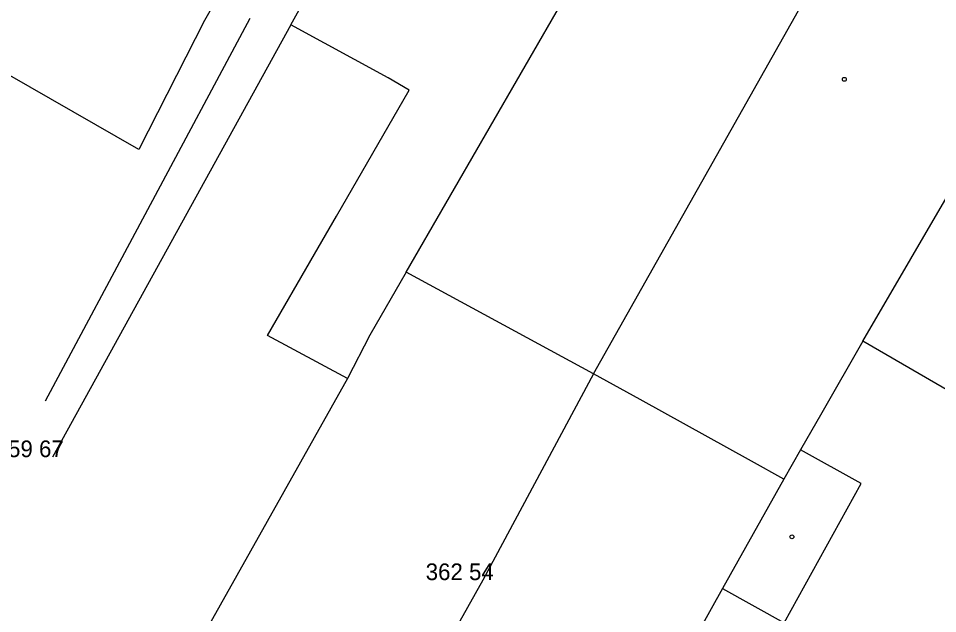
# Model space of a CAD drawing. Extents: x -688316 to -688024, y -973785 to -973591.
# Drawn here: x -688191.59 to -688150.19, y -973719.16 to -973692.34 of the extents above; entities that cross this region are included whole.
import ezdxf

# ---------------------------------------------------------------- set-up
doc = ezdxf.new("R2010")
doc.units = 0
for name, color, linetype in [('Vrstva 12_kanalizace SCVAK', 7, 'Continuous'), ('Vrstva 3', 7, 'Continuous'), ('Vrstva 5', 7, 'Continuous'), ('Vrstva 58', 7, 'Continuous'), ('Vrstva 7', 7, 'Continuous')]:
    doc.layers.add(name, color=color, linetype=linetype)

# ---------------------------------------------------------------- blocks, each defined once
blk = doc.blocks.new('B_NESP')
at = {"layer": 'Vrstva 58'}
blk.add_circle((0, 0), 0.875, dxfattribs=at)

msp = doc.modelspace()

# ---------------------------------------------------------------- linework, layer by layer
at = {"layer": 'Vrstva 12_kanalizace SCVAK'}
msp.add_lwpolyline([(-688181.163, -973692.355), (-688190.388, -973709.588)], dxfattribs=at)
at = {"layer": 'Vrstva 5'}
for p, q in [((-688174.12, -973703.78), (-688160.7, -973680.5)), ((-688165.69, -973708.36), (-688152.56, -973685.09)), ((-688153.55, -973706.89), (-688143.74, -973689.99)), ((-688183.21, -973692.44), (-688186.17, -973698.25)), ((-688186.17, -973698.25), (-688192.08, -973694.85)), ((-688173.99, -973695.57), (-688174.94, -973695.02)), ((-688177.27, -973701.25), (-688173.99, -973695.57)), ((-688178.26, -973702.96), (-688177.27, -973701.25)), ((-688180.38, -973706.63), (-688178.26, -973702.96)), ((-688174.12, -973703.78), (-688175.76, -973706.62)), ((-688165.69, -973708.36), (-688174.12, -973703.78)), ((-688176.77, -973708.56), (-688180.38, -973706.63)), ((-688175.76, -973706.62), (-688176.77, -973708.56)), ((-688153.55, -973706.89), (-688155.4, -973710.12)), ((-688145.05, -973711.82), (-688153.55, -973706.89)), ((-688163.59, -973709.52), (-688165.69, -973708.36)), ((-688158.57, -973712.29), (-688163.59, -973709.52)), ((-688157.11, -973713.1), (-688158.57, -973712.29)), ((-688157.11, -973713.1), (-688159.87, -973718.03))]:
    msp.add_line(p, q, dxfattribs=at)
for points in [[(-688175.06, -973672.3), (-688172.73, -973673.64), (-688172.67, -973673.99), (-688183.21, -973692.44)], [(-688174.94, -973695.02), (-688179.32, -973692.64), (-688178.44, -973691.03)], [(-688155.4, -973710.12), (-688156.36, -973711.78), (-688157.11, -973713.1)], [(-688159.87, -973718.03), (-688157.1, -973719.57), (-688153.63, -973713.29), (-688156.36, -973711.78)]]:
    msp.add_lwpolyline(points, dxfattribs=at)
at = {"layer": 'Vrstva 7'}
for p, q in [((-688179.32, -973692.64), (-688190.05, -973712.11)), ((-688165.69, -973708.36), (-688170.68, -973717.65)), ((-688176.77, -973708.56), (-688190.35, -973732.73)), ((-688170.68, -973717.65), (-688181.99, -973737.94)), ((-688159.87, -973718.03), (-688160.98, -973720))]:
    msp.add_line(p, q, dxfattribs=at)

# ---------------------------------------------------------------- block references
at = {"layer": 'Vrstva 58', "xscale": 0.1, "yscale": 0.10000000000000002}
for p in [(-688154.39, -973695.09), (-688154.39, -973695.09), (-688154.39, -973695.09), (-688154.39, -973695.09), (-688156.75, -973715.7), (-688156.75, -973715.7), (-688156.75, -973715.7), (-688156.75, -973715.7)]:
    msp.add_blockref('B_NESP', p, dxfattribs=at)

# ---------------------------------------------------------------- texts
at = {"layer": 'Vrstva 3'}
for s, p in [('359 67 ', (-688192.616, -973712.11)), ('359 67 ', (-688192.616, -973712.11)), ('359 67 ', (-688192.616, -973712.11)), ('359 67 ', (-688192.616, -973712.11)), ('359 67 ', (-688192.616, -973712.11)), ('359 67 ', (-688192.616, -973712.11)), ('359 67 ', (-688192.616, -973712.11)), ('362 54 ', (-688173.246, -973717.65)), ('362 54 ', (-688173.246, -973717.65)), ('362 54 ', (-688173.246, -973717.65)), ('362 54 ', (-688173.246, -973717.65)), ('362 54 ', (-688173.246, -973717.65)), ('362 54 ', (-688173.246, -973717.65)), ('362 54 ', (-688173.246, -973717.65))]:
    msp.add_text(s, height=0.75, dxfattribs=at).set_placement(p)

doc.saveas('drawing.dxf')
